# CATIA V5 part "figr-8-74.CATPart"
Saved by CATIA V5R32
Part number: Part1
Bounding box of the stored display mesh (mm): x -48 to 48, y -106.879 to 106.685, z -32.702 to 29.91
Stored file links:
  D:\PROJECTS\Project 2022\CATIA V5 6R 2022\Resources\Part Files\c08_catia_v5_6r2022_prt\figr-8-74.CATPart
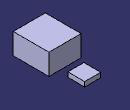
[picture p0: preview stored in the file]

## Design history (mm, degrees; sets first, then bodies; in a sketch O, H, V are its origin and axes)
Body1 (main body)
  Sketch1 on yz-plane, origin (0, 0, 0), H (0, 1, 0), V (0, 0, 1)
    line L1 (-106.8789, 29.9101) -> (0, 29.9101)
    line L2 (0, 29.9101) -> (0, -32.7018)
    line L3 (0, -32.7018) -> (-106.8789, -32.7018)
    line L4 (-106.8789, -32.7018) -> (-106.8789, 29.9101)
    point P3 (0, -32.7018)
    horizontal: L1 H, L3 H
    vertical: L2 V, L4 V
    coincidence: P3 V
  Pad1: profile Sketch1, direction (1, 0, 0), length 48, mirrored extent
  Sketch2 on yz-plane, origin (0, 0, 0), H (0, 1, 0), V (0, 0, 1)
    line L1 (56.3417, 7.481) -> (106.6854, 7.481)
    line L2 (106.6854, 7.481) -> (106.6854, -6.5572)
    line L3 (106.6854, -6.5572) -> (56.3417, -6.5572)
    line L4 (56.3417, -6.5572) -> (56.3417, 7.481)
    horizontal: L1 H, L3 H
    vertical: L2 V, L4 V
  Pad2: profile Sketch2, direction (1, 0, 0), length 48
